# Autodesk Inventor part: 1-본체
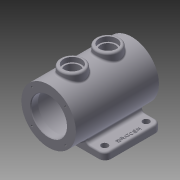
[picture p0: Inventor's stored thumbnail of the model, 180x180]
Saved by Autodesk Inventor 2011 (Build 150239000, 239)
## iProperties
Created: 2014-12
Part Number: 1-본체
Document SubType Name: Modeling
Designer: user
Density: 2.71 g/cm^3
Material: 알루미늄-6061
Mass: 1293.19 g
Surface Area: 1040.06 cm^2
Volume: 477.193 cm^3
Author: user
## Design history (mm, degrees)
sketch "스케치1"
  geometry: L1 (-65, -47.5)-(65, -47.5); L2 (65, -47.5)-(65, 47.5); L3 (65, 47.5)-(-65, 47.5); L4 (-65, 47.5)-(-65, -47.5); L5 (-65, -47.5)-(65, 47.5); 2 further points
  constraints: 10 end point, 2 parallel, 1 coincident, 1 horizontal, 1 midpoint, 1 perpendicular
  dimensions: "d0" = 95 distance of L3.end L1.start; "d1" = 130 distance of L2.end L3.end
extrude "돌출1" new body sketch "스케치1" distance "d2" = 12; taper "d3" = 0 deg
node "작업 평면1"
sketch "스케치2"
  geometry: L1 (0, -12)-(130, -12) reference; L2 (130, 0)-(130, -12) reference; L3 (130, 0)-(0, 0) reference; L4 (0, 0)-(0, -12) reference; C1 r 46 at (65, -50); 2 further points
  constraints: 1 centre point, 1 midpoint, 1 vertical alignment
  dimensions: "d5" = 92 diameter of C1; "d6" = 50 distance from line of L3 C1.centre
extrude "돌출2" join sketch "스케치2" distance "d7" = 140; taper "d8" = 0 deg
sketch "스케치3"
  geometry: L1 (-77.5, 96)-(62.5, 96) reference; L2 (62.5, 96)-(62.5, 4) reference; L3 (62.5, 4)-(47.5, 4) reference; L4 (47.5, 4)-(47.5, 0) reference; L5 (47.5, 0)-(-47.5, 0) reference; L6 (-47.5, 0)-(-47.5, 4) reference; L7 (-47.5, 4)-(-77.5, 4) reference; L8 (-77.5, 4)-(-77.5, 96) reference; L9 (-77.5, 50)-(62.5, 50); L10 (-77.5, 80)-(-65.5, 80); L11 (-65.5, 80)-(-65.5, 84.5); L12 (-62.5, 87.5)-(47.5, 87.5); L13 (50.5, 84.5)-(50.5, 80); L14 (50.5, 80)-(62.5, 80); A1 r 3 centre (-62.5, 84.5) between (-62.5, 87.5) and (-65.5, 84.5); A2 r 3 centre (47.5, 84.5) between (50.5, 84.5) and (47.5, 87.5); 1 further point
  constraints: 12 end point, 4 point on circle, 4 tangent, 3 perpendicular, 2 centre point, 2 midpoint, 2 parallel, 2 point on line, 1 equal radius, 1 vertical
  dimensions: "d10" = 60 diameter of L14 L9; "d11" = 60 diameter of L10 L9; "d12" = 75 diameter of L12 L9; "d13" = 12 distance of L13.end L14.end; "d14" = 12 distance of L10.start L10.end; "d15" = 3 radius of A1
revolve "회전1" sketch "스케치3" stored, may be unused: angle "d16" = 90 deg
chamfer "모따기1" distance "d17" = 1; stored, may be unused: second distance "d18" = 2, angle "d19" = 45 deg
node "작업 평면2"
sketch "스케치4"
  geometry: L1 (25.923, -47.5)-(-25.923, -47.5) reference; L2 (-46, 62.5)-(46, 62.5) reference; L3 (46, -77.5)-(-46, -77.5) reference; L4 (25.923, -47.5)-(-25.923, -47.5) reference; L5 (25.923, 47.5)-(25.923, -47.5) reference; L6 (-25.923, 47.5)-(25.923, 47.5) reference; L7 (-25.923, -47.5)-(-25.923, 47.5) reference; C1 r 20 at (0, -37.5); C2 r 20 at (0, 22.5); 1 further point
  constraints: 2 centre point, 2 vertical alignment
  dimensions: "d21" = 40 diameter of C1; "d22" = 40 diameter of C2; "d23" = 40 distance from line of C1.centre L3; "d24" = 40 distance from line of C2.centre L2
extrude "돌출3" join sketch "스케치4" stored distance "d25" = 140; taper "d26" = 0 deg
hole "Hole1" diameter "d29" = 25; stored, may be unused: countersink angle "d33" = 90 deg, drill point angle "d35" = 118 deg; dims "d27" = 10, "d28" = 10, "d30" = 6, "d31" = 30, "d32" = 8, "d34" = 50
hole "Hole2" diameter "d38" = 25; stored, may be unused: countersink angle "d42" = 90 deg, drill point angle "d44" = 118 deg; dims "d36" = 10, "d37" = 10, "d39" = 6, "d40" = 30, "d41" = 8, "d43" = 50
sketch "스케치5"
  geometry: L1 (25.923, 47.5)-(65, 47.5) reference; L2 (25.923, 62.5)-(25.923, 47.5) reference; L3 (25.923, 47.5)-(25.923, -47.5) reference; L4 (65, -47.5)-(25.923, -47.5) reference; L5 (65, 47.5)-(65, -47.5) reference; L6 (25.923, 47.5)-(65, 47.5) reference; L7 (-25.923, 62.5)-(25.923, 62.5) reference; L8 (-25.923, 47.5)-(-25.923, 62.5) reference; L9 (-65, 47.5)-(-25.923, 47.5) reference; L10 (-65, -47.5)-(-65, 47.5) reference; L11 (-25.923, -47.5)-(-65, -47.5) reference; L12 (-25.923, -77.5)-(-25.923, -47.5) reference; L13 (25.923, -77.5)-(-25.923, -77.5) reference; L14 (25.923, -47.5)-(25.923, -77.5) reference; L15 (-25.923, -47.5)-(-25.923, 47.5) reference; L16 (0, 0)-(-6.222, 0); C1 r 5.5 at (-52, 35); C2 r 5.5 at (52, 35); C3 r 5.5 at (52, -35); C4 r 5.5 at (-52, -35)
  constraints: 4 centre point, 2 end point, 2 symmetric about line, 1 horizontal, 2 other
  dimensions: "d45" = 11 diameter of C1; "d46" = 11 diameter of C2; "d47" = 104 distance of C2.centre C1.centre; "d48" = 52 horizontal distance of C2.centre L16.start; "d49" = 12.5 distance from line of C1.centre L9; "d50" = 12.5 distance from line of L1 C2.centre
extrude "돌출4" cut sketch "스케치5" stored distance "d51" = 140; taper "d52" = 0 deg
sketch "스케치6"
  geometry: L1 (0, 0)-(-40, 0); L2 (0, 0)-(-28.284, 28.284); C1 r 31 at (0, 0) reference; 1 further point
  constraints: 4 end point, 1 horizontal
  dimensions: "d53" = 40 distance of L1.start L1.end; "d54" = 40 distance of L1.start L2.end; "d55" = 45 deg angle of L2 L1
hole "Hole3" sketch "스케치6" at (-28.284, 28.284) diameter "d56" = 3.242; stored, may be unused: countersink angle "d60" = 90 deg, drill point angle "d62" = 118 deg; dims "d57" = 8, "d58" = 30, "d59" = 8, "d61" = 10
node "작업 평면3"
sketch "스케치7"
  geometry: L1 (65, 47.5)-(65, -47.5) reference; L2 (53.998, -20.739)-(53.998, 20.739); L3 (53.998, 20.739)-(60.002, 20.739); L4 (60.002, 20.739)-(60.002, -20.739); L5 (60.002, -20.739)-(53.998, -20.739); L6 (53.998, -20.739)-(60.002, 20.739); C1 r 5.5 at (52, -35) reference; 3 further points
  constraints: 2 end point, 1 coincident, 1 midpoint, 2 other
  dimensions: "d67" = 8 distance from line of L1 point (57, 0); "d68" = 35 vertical distance of point (57, 0) C1.centre
feature "엠보싱1" sketch "스케치7" dims "d0" = 95, "d1" = 130, "d69" = 1, "d70" = 0
fillet "모깎기1" dims "d71" = 5
fillet "모깎기2" dims "d72" = 10
fillet "모깎기3" dims "d73" = 3
fillet "모깎기4" dims "d74" = 3
node "솔리드1"
pattern_circular "원형 패턴1" dims angle "d64" = 360 deg
mirror "대칭1"
node "투영된 루프1"
node "투영된 루프2"
node "절단 모서리 투영1"
node "절단 모서리 투영2"
other parameters: "d4" = 15, "d20" = 106
